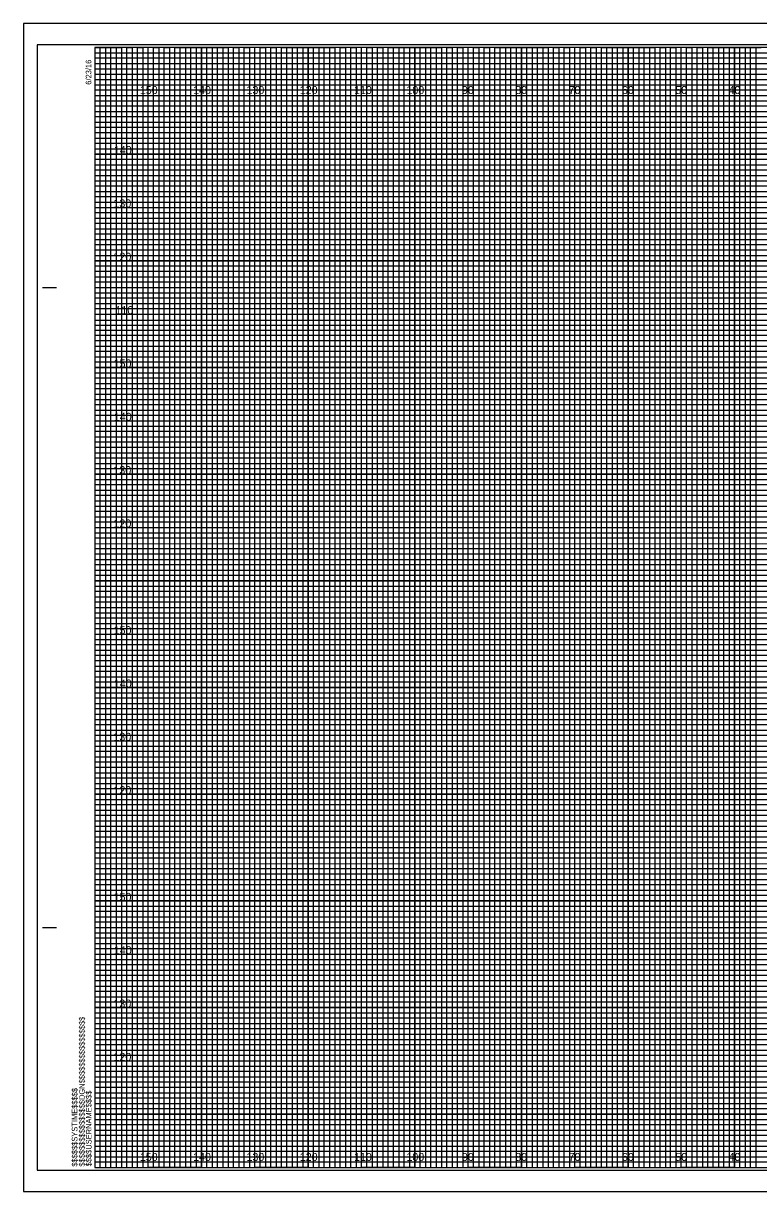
# Model space of a CAD drawing. Extents: x -13 to 323, y -5 to 1754.
# Drawn here: x -13.4 to 124.5, y 435.5 to 654.5 of the extents above; entities that cross this region are included whole.
import ezdxf

# ---------------------------------------------------------------- set-up
doc = ezdxf.new("R2010")
doc.units = 0
for name, color, linetype in [('Exist Cross Section Cell', 7, 'Continuous'), ('Exist XS Center Line Elevation Label', 7, 'Continuous'), ('Exist XS Ground Line', 7, 'Continuous'), ('Prop CMT Pvmt Course 1', 7, 'Continuous'), ('Prop CMT Pvmt Course 3', 7, 'Continuous'), ('Prop CMT Pvmt Surface', 7, 'Continuous'), ('Prop CMT Pvmt Surface Shoulder', 7, 'Continuous'), ('Prop CMT Shld Paved Course 1', 7, 'Continuous'), ('Prop CMT Shld Paved Course 2', 7, 'Continuous'), ('Prop CMT Shld Paved Course 3', 7, 'Continuous'), ('Prop CMT Subgrade Earthwork', 7, 'Continuous')]:
    doc.layers.add(name, color=color, linetype=linetype)

msp = doc.modelspace()

# ---------------------------------------------------------------- linework, layer by layer
at = {"layer": 'Exist XS Center Line Elevation Label'}
for points in [[(0, 650), (5, 650), (5, 440), (15, 440), (15, 650), (25, 650), (25, 440), (35, 440), (35, 650), (45, 650), (45, 440), (55, 440), (55, 650), (65, 650), (65, 440), (75, 440), (75, 650), (85, 650), (85, 440), (95, 440), (95, 650), (105, 650), (105, 440), (115, 440), (115, 650), (125, 650)], [(0, 645), (275, 645)], [(0, 625), (320, 625), (320, 635), (0, 635)], [(0, 605), (320, 605), (320, 615), (0, 615)], [(0, 585), (320, 585), (320, 595), (0, 595)], [(0, 565), (320, 565), (320, 575), (0, 575)], [(0, 545), (320, 545), (320, 555), (0, 555)], [(0, 525), (320, 525), (320, 535), (0, 535)], [(0, 505), (320, 505), (320, 515), (0, 515)], [(0, 485), (320, 485), (320, 495), (0, 495)], [(0, 465), (320, 465), (320, 475), (0, 475)], [(0, 445), (320, 445), (320, 455), (0, 455)]]:
    msp.add_lwpolyline(points, dxfattribs=at)
at = {"layer": 'Exist XS Ground Line'}
for p, q in [((10, 650), (0, 650)), ((10, 440), (10, 650)), ((30, 650), (20, 650)), ((20, 650), (20, 440)), ((30, 440), (30, 650)), ((50, 650), (40, 650)), ((40, 650), (40, 440)), ((50, 440), (50, 650)), ((70, 650), (60, 650)), ((60, 650), (60, 440)), ((70, 440), (70, 650)), ((90, 650), (80, 650)), ((80, 650), (80, 440)), ((90, 440), (90, 650)), ((110, 650), (100, 650)), ((100, 650), (100, 440)), ((110, 440), (110, 650)), ((130, 650), (120, 650)), ((120, 650), (120, 440)), ((20, 440), (10, 440)), ((40, 440), (30, 440)), ((60, 440), (50, 440)), ((80, 440), (70, 440)), ((100, 440), (90, 440)), ((120, 440), (110, 440))]:
    msp.add_line(p, q, dxfattribs=at)
for points in [[(0, 640), (320, 640), (320, 630), (0, 630)], [(0, 620), (320, 620), (320, 610), (0, 610)], [(0, 600), (320, 600), (320, 590), (0, 590)], [(0, 580), (320, 580), (320, 570), (0, 570)], [(0, 560), (320, 560), (320, 550), (0, 550)], [(0, 540), (320, 540), (320, 530), (0, 530)], [(0, 520), (320, 520), (320, 510), (0, 510)], [(0, 500), (320, 500), (320, 490), (0, 490)], [(0, 480), (320, 480), (320, 470), (0, 470)], [(0, 460), (320, 460), (320, 450), (0, 450)]]:
    msp.add_lwpolyline(points, dxfattribs=at)
at = {"layer": 'Prop CMT Pvmt Course 3'}
msp.add_lwpolyline([(-13.4, 435.5), (323.3, 435.5), (323.3, 654.5), (-13.4, 654.5)], close=True, dxfattribs=at)
at = {"layer": 'Prop CMT Pvmt Surface'}
for p, q in [((10, 440), (10, 650)), ((20, 440), (20, 650)), ((30, 440), (30, 650)), ((40, 440), (40, 650)), ((50, 440), (50, 650)), ((60, 440), (60, 650)), ((70, 440), (70, 650)), ((80, 440), (80, 650)), ((90, 440), (90, 650)), ((100, 440), (100, 650)), ((110, 440), (110, 650)), ((120, 440), (120, 650)), ((0, 640), (320, 640)), ((0, 630), (320, 630)), ((0, 620), (320, 620)), ((0, 610), (320, 610)), ((0, 600), (320, 600)), ((0, 590), (320, 590)), ((0, 580), (320, 580)), ((0, 570), (320, 570)), ((0, 560), (320, 560)), ((0, 550), (320, 550)), ((0, 540), (320, 540)), ((0, 530), (320, 530)), ((0, 520), (320, 520)), ((0, 510), (320, 510)), ((0, 500), (320, 500)), ((0, 490), (320, 490)), ((0, 480), (320, 480)), ((0, 470), (320, 470)), ((0, 460), (320, 460)), ((0, 450), (320, 450))]:
    msp.add_line(p, q, dxfattribs=at)
at = {"layer": 'Prop CMT Pvmt Surface Shoulder'}
for p, q in [((323.3, 654.5), (-13.4, 654.5)), ((-13.4, 654.5), (-13.4, 435.5)), ((-13.4, 435.5), (323.3, 435.5))]:
    msp.add_line(p, q, dxfattribs=at)
at = {"layer": 'Prop CMT Shld Paved Course 1'}
for p, q in [((0, 649), (260, 649)), ((260, 647.98), (0, 647.98)), ((0, 647.98), (0, 647)), ((0, 647), (260, 647)), ((260, 645.89), (0, 645.89)), ((0, 645.89), (0, 644)), ((0, 644), (320, 644))]:
    msp.add_line(p, q, dxfattribs=at)
for points in [[(0, 643), (270, 643), (320, 643), (320, 642), (0, 642)], [(0, 641), (320, 641), (320, 639), (0, 639)], [(0, 638), (320, 638), (320, 637), (0, 636.98)], [(0, 636), (320, 636), (320, 634), (0, 634)], [(0, 633), (320, 633), (320, 632), (0, 632)], [(0, 631), (320, 631), (320, 629), (0, 629)], [(0, 628), (320, 628), (320, 627), (0, 627)], [(0, 626), (320, 626), (320, 624), (0, 624)], [(0, 623), (320, 623), (320, 622), (0, 622)], [(0, 621), (320, 621), (320, 619), (0, 619)], [(0, 618), (320, 618), (320, 617), (0, 617)], [(0, 616), (320, 616), (320, 613.95), (320, 613), (320, 612), (0, 612)], [(0, 614), (320, 614), (320, 613), (0, 613)], [(0, 611), (320, 611), (320, 609), (0, 609.03)], [(0, 609.03), (320, 609), (320, 608), (0, 608)], [(0, 607), (320, 607), (320, 606), (0, 606)], [(0, 604), (320, 604), (320, 603), (0, 603)], [(0, 602), (320, 602), (320, 601), (0, 601)], [(-0.07, 598.89), (320, 598.89), (320, 597.88), (-0.07, 597.88)], [(0, 597), (320, 597), (320, 596), (0, 596)], [(0, 594), (320, 594), (320, 593), (0, 593)], [(0, 592), (320, 592), (320, 591), (0, 591)], [(0, 589), (320, 589), (320, 588), (0, 588)], [(0, 587), (320, 587), (320, 586), (0, 586)], [(0, 584), (320, 584), (320, 583), (0, 583)], [(0, 582), (320, 582), (320, 581), (0, 581)], [(0, 579), (320, 579), (319.99, 577.98), (0, 578)], [(0, 577), (320, 577), (320, 576), (0, 576)], [(0, 574), (320, 574), (320, 573), (0, 573)], [(0, 572), (320, 572), (320, 571), (0, 571)], [(0, 569), (320, 569), (320, 568), (0, 568)], [(0, 567), (320, 567), (320, 566), (0, 566)], [(0, 564), (320, 564), (320, 563), (0, 563)], [(0, 562), (320, 562), (320, 561), (0, 561)], [(0, 559), (320, 559), (320, 558), (0, 558)], [(0, 556.99), (320.07, 556.91), (320, 556), (0, 556)], [(0, 554), (320, 554), (320, 553), (0, 553)], [(0, 552), (320, 552), (320, 551), (0, 551)], [(0, 549), (320, 549), (320, 548), (0, 548)], [(0, 547), (320, 547), (320, 546), (0, 546)], [(0, 544), (320, 544), (320, 543), (0, 543)], [(0, 542), (320, 542), (320, 541), (0, 541)], [(0, 539), (320, 539), (320, 538), (0, 538)], [(0, 537), (320, 537), (320, 536), (0, 536)], [(0, 534), (320, 534), (320, 533), (0, 533)], [(0, 532), (320, 532), (320, 531), (0, 531)], [(0, 529), (320, 529), (320, 528), (0, 528)], [(0, 527), (320, 527), (320, 526), (0, 526)], [(0, 524), (320, 524), (320, 523), (0, 523)], [(0, 522), (320, 522), (320, 521), (0, 521)], [(0, 519), (320, 519), (319.99, 517.98), (0, 518)], [(0, 517), (320, 517), (320, 516), (0, 516)], [(0, 514), (320, 514), (320, 513), (0, 513)], [(0, 512), (320, 512), (320, 511), (0, 511)], [(0, 509), (320, 509), (320, 508), (0, 508)], [(0, 507), (320, 507), (320, 506), (0, 506)], [(0, 504), (320, 504), (320, 503), (0, 503)], [(0, 502), (320, 502), (320, 501), (0, 501)], [(0, 499), (320, 499), (320, 498), (0, 498)], [(0, 496.99), (320.07, 496.91), (320, 496), (0, 496)], [(0, 494), (320, 494), (320, 493), (0, 493)], [(0, 492), (320, 492), (320, 491), (0, 491)], [(0, 489), (320, 489), (320, 488), (0, 488)], [(0, 487), (320, 487), (320, 486), (0, 486)], [(0, 484), (320, 484), (320, 483), (0, 483)], [(0, 482), (320, 482), (320, 481), (0, 481)], [(0, 479), (320, 479), (320, 478), (0, 478)], [(0, 477), (320, 477), (320, 476), (0, 476)], [(0, 474), (320, 474), (320, 473), (0, 473)], [(0, 472), (320, 472), (320, 471), (0, 471)], [(0, 469), (320, 469), (320, 468), (0, 468)], [(0, 467), (320, 467), (320, 466), (0, 466)], [(0, 464), (320, 464), (320, 463), (0, 463)], [(0, 462), (320, 462), (320, 461), (0, 461)], [(0, 459), (320, 459), (320, 458), (0, 458)], [(0, 457), (320, 457), (320, 456), (0, 456)], [(0, 454), (320, 454), (320, 453), (0, 453)], [(0, 452), (320, 452), (320, 451), (0, 451)], [(0, 449), (320, 449), (320, 448), (0, 448)], [(0, 447), (320, 447), (320, 446), (0, 446)], [(0, 444), (320, 444), (320, 443), (0, 443)], [(0, 442), (320, 442), (320, 441), (0, 441)]]:
    msp.add_lwpolyline(points, dxfattribs=at)
at = {"layer": 'Prop CMT Shld Paved Course 2'}
for p, q in [((-9.8, 605), (-7.3, 605)), ((-9.7, 605), (-7.2, 605)), ((-9.8, 485), (-7.3, 485)), ((-9.7, 485), (-7.2, 485)), ((0, 440), (0, 440)), ((0, 440), (0, 440)), ((0, 440), (0, 440)), ((0, 440), (0, 440)), ((0, 440), (0, 440)), ((0, 440), (0, 440)), ((0, 440), (0, 440))]:
    msp.add_line(p, q, dxfattribs=at)
msp.add_lwpolyline([(320, 650), (0, 650), (0, 440), (320, 440)], close=True, dxfattribs=at)
at = {"layer": 'Prop CMT Shld Paved Course 3'}
for points in [[(0, 440), (1, 440), (1, 650), (2, 650), (2, 440)], [(2, 440), (3, 440), (3, 650), (4, 650), (4, 440)], [(5, 440), (6, 440), (6, 650), (7, 650), (7, 440)], [(7, 440), (8, 440), (8, 650), (9, 650), (9, 440)], [(10, 440), (11, 440), (11, 650), (12, 650), (12, 440)], [(12, 440), (13, 440), (13, 650), (14, 650), (14, 440)], [(15, 440), (16, 440), (16, 650), (17, 650), (17, 440)], [(17, 440), (18, 440), (18, 650), (19, 650), (19, 440)], [(20, 440), (21, 440), (21, 650), (22, 650), (22, 440)], [(22, 440), (23, 440), (23, 650), (24, 650), (24, 440)], [(25, 440), (26, 440), (26, 650), (27, 650), (27, 440)], [(27, 440), (28, 440), (28, 650), (29, 650), (29, 440)], [(30, 440), (31, 440), (31, 650), (32, 650), (32, 440)], [(32, 440), (33, 440), (33, 650), (34, 650), (34, 440)], [(35, 440), (36, 440), (36, 650), (37, 650), (37, 440)], [(37, 440), (38, 440), (38, 650), (39, 650), (39, 440)], [(40, 440), (41, 440), (41, 650), (42, 650), (42, 440)], [(42, 440), (43, 440), (43, 650), (44, 650), (44, 440)], [(45, 440), (46, 440), (46, 650), (47, 650), (47, 440)], [(47, 440), (48, 440), (48, 650), (49, 650), (49, 440)], [(50, 440), (51, 440), (51, 650), (52, 650), (52, 440)], [(52, 440), (53, 440), (53, 650), (54, 650), (54, 440)], [(55, 440), (56, 440), (56, 650), (57, 650), (57, 440)], [(57, 440), (58, 440), (58, 650), (59, 650), (59, 440)], [(60, 440), (61, 440), (61, 650), (62, 650), (62, 440)], [(62, 440), (63, 440), (63, 650), (64, 650), (64, 440)], [(65, 440), (66, 440), (66, 650), (67, 650), (67, 440)], [(67, 440), (68, 440), (68, 650), (69, 650), (69, 440)], [(70, 440), (71, 440), (71, 650), (72, 650), (72, 440)], [(72, 440), (73, 440), (73, 650), (74, 650), (74, 440)], [(75, 440), (76, 440), (76, 650), (77, 650), (77, 440)], [(77, 440), (78, 440), (78, 650), (79, 650), (79, 440)], [(80, 440), (81, 440), (81, 650), (82, 650), (82, 440)], [(82, 440), (83, 440), (83, 650), (84, 650), (84, 440)], [(85, 440), (86, 440), (86, 650), (87, 650), (87, 440)], [(87, 440), (88, 440), (88, 650), (89, 650), (89, 440)], [(90, 440), (91, 440), (91, 650), (92, 650), (92, 440)], [(92, 440), (93, 440), (93, 650), (94, 650), (94, 440)], [(95, 440), (96, 440), (96, 650), (97, 650), (97, 440)], [(97, 440), (98, 440), (98, 650), (99, 650), (99, 440)], [(100, 440), (101, 440), (101, 650), (102, 650), (102, 440)], [(102, 440), (103, 440), (103, 650), (104, 650), (104, 440)], [(105, 440), (106, 440), (106, 650), (107, 650), (107, 440)], [(107, 440), (108, 440), (108, 650), (109, 650), (109, 440)], [(110, 440), (111, 440), (111, 650), (112, 650), (112, 440)], [(112, 440), (113, 440), (113, 650), (114, 650), (114, 440)], [(115, 440), (116, 440), (116, 650), (117, 650), (117, 440)], [(117, 440), (118, 440), (118, 650), (119, 650), (119, 440)], [(120, 440), (121, 440), (121, 650), (122, 650), (122, 440)], [(122, 440), (123, 440), (123, 650), (124, 650), (124, 440)]]:
    msp.add_lwpolyline(points, dxfattribs=at)
at = {"layer": 'Prop CMT Subgrade Earthwork'}
msp.add_lwpolyline([(-10.8, 439.5), (322.4, 439.5), (322.4, 650.5), (-10.8, 650.5)], close=True, dxfattribs=at)

# ---------------------------------------------------------------- texts
at = {"layer": 'Exist Cross Section Cell'}
for s, p in [('150', (8.44, 641.25)), ('140', (18.44, 641.25)), ('130', (28.44, 641.25)), ('120', (38.44, 641.25)), ('110', (48.62, 641.25)), ('100', (58.44, 641.25)), ('90', (68.86, 641.25)), ('80', (78.86, 641.25)), ('70', (88.86, 641.25)), ('60', (98.86, 641.25)), ('50', (108.86, 641.25)), ('40', (118.86, 641.25)), ('150', (8.44, 441.25)), ('140', (18.44, 441.25)), ('130', (28.44, 441.25)), ('120', (38.44, 441.25)), ('110', (48.62, 441.25)), ('100', (58.44, 441.25)), ('90', (68.86, 441.25)), ('80', (78.86, 441.25)), ('70', (88.86, 441.25)), ('60', (98.86, 441.25)), ('50', (108.86, 441.25)), ('40', (118.86, 441.25))]:
    msp.add_text(s, height=1.5, dxfattribs=at).set_placement(p)
at = {"layer": 'Prop CMT Pvmt Course 1'}
for s, p in [('140', (3.57, 630)), ('130', (3.49, 620)), ('120', (3.5, 610)), ('110', (3.88, 600)), ('150', (3.52, 590)), ('140', (3.57, 580)), ('130', (3.49, 570)), ('120', (3.5, 560)), ('150', (3.52, 540)), ('140', (3.57, 530)), ('130', (3.49, 520)), ('120', (3.5, 510)), ('150', (3.52, 490)), ('140', (3.57, 480)), ('130', (3.49, 470)), ('120', (3.5, 460))]:
    msp.add_text(s, height=1.5, dxfattribs=at).set_placement(p)
at = {"layer": 'Prop CMT Shld Paved Course 2'}
for s, p in [('6/23/16', (-0.65, 643)), ('$$$$$$$$$$$$$$$$DGN$$$$$$$$$$$$$$$$', (-1.88, 440.18)), ('$$$$$$SYSTIME$$$$$', (-3.26, 440.18)), ('$$$$USERNAME$$$$', (-0.62, 440.23))]:
    msp.add_text(s, height=1.05, rotation=90, dxfattribs=at).set_placement(p)

doc.saveas('drawing.dxf')
